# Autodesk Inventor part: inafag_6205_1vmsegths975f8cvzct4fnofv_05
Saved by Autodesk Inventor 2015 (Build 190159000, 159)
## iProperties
Company: TraceParts S.A.
Created: 2012-12
Part Number: inafag_6205_1vmsegths975f8cvzct4fnofv_05
Checked By: TraceParts S.A.
Catalog Web Link: www.traceparts.com
Document SubType Name: Modeling
Designer: TraceParts
Material: Generic
Density: 1 g/cm^3
Appearance: Default
Author: TraceParts
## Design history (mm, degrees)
feature "inafag_6205_1vmsegths975f8cvzct4fnofv"
body "Solid1"
